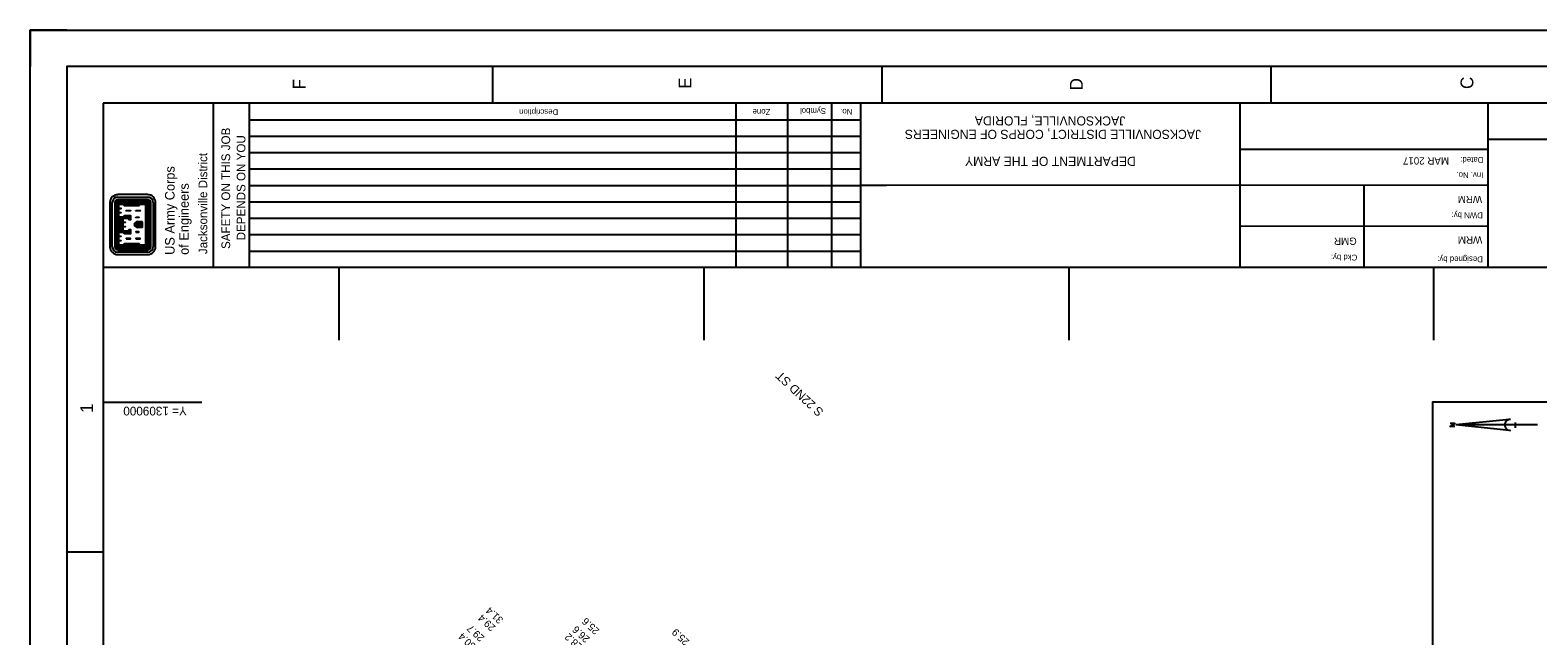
# Model space of a CAD drawing. Extents: x 515576 to 518976, y 1305110 to 1309511.
# Drawn here: x 515576 to 517642, y 1308680 to 1309510 of the extents above; entities that cross this region are included whole.
import ezdxf

# ---------------------------------------------------------------- set-up
doc = ezdxf.new("R2010")
doc.units = 0
for name, color, linetype in [('G-ANNO-NPLT', 7, 'Continuous'), ('G-ANNO-TEXT-DRWG', 7, 'Continuous'), ('G-ANNO-TEXT-LOGO', 7, 'Continuous'), ('G-ANNO-TEXT-PROJ', 7, 'Continuous'), ('G-ANNO-TEXT-TTLB', 7, 'Continuous'), ('G-ANNO-TTLB', 7, 'Continuous'), ('V-ANNO-SYMB', 7, 'Continuous'), ('V-ROAD-IDEN', 7, 'Continuous'), ('V-TOPO-COOR-STAT', 7, 'Continuous'), ('V-TOPO-SOUN', 7, 'Continuous')]:
    doc.layers.add(name, color=color, linetype=linetype)

msp = doc.modelspace()

# ---------------------------------------------------------------- linework, layer by layer
at = {"layer": 'G-ANNO-NPLT'}
msp.add_lwpolyline([(515576.5, 1305110.5), (515576.5, 1309510.4), (518976.4, 1309510.4), (518976.4, 1305110.5)], close=True, dxfattribs=at)
msp.add_lwpolyline([(515626.5, 1309510.4), (515576.5, 1309510.4), (515576.5, 1309460.4)], dxfattribs=at)
at = {"layer": 'G-ANNO-TEXT-LOGO'}
for p, q in [((515737.5, 1309285), (515696.5, 1309285)), ((515696.5, 1309281.7), (515737.5, 1309281.7)), ((515685.8, 1309274.3), (515685.8, 1309213.5)), ((515689, 1309213.5), (515689, 1309274.3)), ((515692.4, 1309274.3), (515692.4, 1309213.5)), ((515693.3, 1309274.3), (515693.3, 1309213.5)), ((515694.2, 1309274.3), (515694.2, 1309213.5)), ((515695, 1309274.3), (515695, 1309213.5)), ((515695.9, 1309274.3), (515695.9, 1309213.5)), ((515696.5, 1309278.3), (515737.5, 1309278.3)), ((515696.5, 1309277.4), (515737.5, 1309277.4)), ((515696.5, 1309276.5), (515737.5, 1309276.5)), ((515696.5, 1309275.7), (515737.5, 1309275.7)), ((515696.5, 1309274.8), (515737.5, 1309274.8)), ((515696.5, 1309273.9), (515737.2, 1309273.9)), ((515696.5, 1309273.1), (515736.3, 1309273.1)), ((515705.3, 1309272.4), (515726.1, 1309272.4)), ((515706.1, 1309271.5), (515725.2, 1309271.5)), ((515736.3, 1309273.1), (515736.3, 1309214.7)), ((515737.2, 1309273.9), (515737.2, 1309213.9)), ((515738.1, 1309274.3), (515738.1, 1309213.5)), ((515738.9, 1309274.3), (515738.9, 1309213.5)), ((515739.8, 1309274.3), (515739.8, 1309213.5)), ((515740.7, 1309274.3), (515740.7, 1309213.5)), ((515741.5, 1309274.3), (515741.5, 1309213.5)), ((515745, 1309274.3), (515745, 1309213.5)), ((515748.3, 1309213.5), (515748.3, 1309274.3)), ((515696.7, 1309234.6), (515696.7, 1309253.2)), ((515697.6, 1309234.6), (515697.6, 1309253.2)), ((515698.4, 1309234.6), (515698.4, 1309253.2)), ((515699.3, 1309234.6), (515699.3, 1309253.2)), ((515700.2, 1309234.6), (515700.2, 1309253.2)), ((515701, 1309234.6), (515701, 1309253.2)), ((515701.9, 1309234.6), (515701.9, 1309253.2)), ((515730.4, 1309247.9), (515723.7, 1309247.9)), ((515730.4, 1309247.1), (515723.7, 1309247.1)), ((515730.4, 1309246.2), (515723.7, 1309246.2)), ((515730.4, 1309245.3), (515723.7, 1309245.3)), ((515730.4, 1309244.5), (515723.7, 1309244.5)), ((515730.4, 1309243.3), (515723.7, 1309243.3)), ((515730.4, 1309242.5), (515723.7, 1309242.5)), ((515730.4, 1309241.6), (515723.7, 1309241.6)), ((515730.4, 1309240.7), (515723.7, 1309240.7)), ((515730.4, 1309239.9), (515723.7, 1309239.9)), ((515730.4, 1309239.9), (515730.4, 1309247.9)), ((515696.5, 1309214.7), (515736.3, 1309214.7)), ((515696.5, 1309213.9), (515737.2, 1309213.9)), ((515696.5, 1309213), (515737.5, 1309213)), ((515696.5, 1309212.1), (515737.5, 1309212.1)), ((515696.5, 1309211.2), (515737.5, 1309211.2)), ((515696.5, 1309210.4), (515737.5, 1309210.4)), ((515696.5, 1309209.5), (515737.5, 1309209.5)), ((515737.5, 1309206), (515696.5, 1309206)), ((515696.5, 1309202.8), (515737.5, 1309202.8)), ((515705.2, 1309215.4), (515726.2, 1309215.4)), ((515706.1, 1309216.3), (515725.2, 1309216.3))]:
    msp.add_line(p, q, dxfattribs=at)
for points in [[(515696.5, 1309215.4), (515704.4, 1309215.4), (515706.1, 1309217.1), (515725.2, 1309217.1), (515727, 1309215.4), (515735.7, 1309215.4), (515735.7, 1309272.4), (515727, 1309272.4), (515725.2, 1309270.6), (515706.1, 1309270.6), (515704.4, 1309272.4), (515696.5, 1309272.4), (515696.5, 1309264.9), (515696.5, 1309259.1), (515696.5, 1309253.7), (515704.4, 1309253.7), (515706.1, 1309255.6), (515713.1, 1309255.6), (515713.1, 1309251.4), (515712.4, 1309251.4), (515710.6, 1309253.2), (515702.8, 1309253.2), (515702.8, 1309245.7), (515702.8, 1309239.9), (515702.8, 1309234.6), (515710.6, 1309234.6), (515712.4, 1309236.4), (515713.1, 1309236.4), (515713.1, 1309232.2), (515706.1, 1309232.2), (515704.4, 1309234), (515696.5, 1309234), (515696.5, 1309226.5), (515696.5, 1309220.7), (515696.5, 1309215.4)], [(515697.4, 1309216.2), (515704, 1309216.2), (515705.8, 1309218), (515725.6, 1309218), (515727.4, 1309216.2), (515734.8, 1309216.2), (515734.8, 1309271.6), (515727.4, 1309271.6), (515725.6, 1309269.7), (515705.8, 1309269.7), (515704, 1309271.6), (515697.4, 1309271.6), (515697.4, 1309266.2), (515700.5, 1309266.2), (515700.5, 1309265.7), (515697.4, 1309265.7), (515697.4, 1309260.4), (515700.5, 1309260.4), (515700.5, 1309260), (515697.4, 1309260), (515697.4, 1309254.6), (515704, 1309254.6), (515705.8, 1309256.4), (515713.9, 1309256.4), (515713.9, 1309250.6), (515712, 1309250.6), (515710.2, 1309252.4), (515703.6, 1309252.4), (515703.6, 1309247), (515706.7, 1309247), (515706.7, 1309246.6), (515703.6, 1309246.6), (515703.6, 1309241.2), (515706.7, 1309241.2), (515706.7, 1309240.7), (515703.6, 1309240.7), (515703.6, 1309235.4), (515710.2, 1309235.4), (515712, 1309237.2), (515713.9, 1309237.2), (515713.9, 1309231.4), (515705.8, 1309231.4), (515704, 1309233.2), (515697.4, 1309233.2), (515697.4, 1309227.9), (515700.5, 1309227.9), (515700.5, 1309227.4), (515697.4, 1309227.4), (515697.4, 1309222), (515700.5, 1309222), (515700.5, 1309221.6), (515697.4, 1309221.6), (515697.4, 1309216.2)], [(515708.1, 1309263.3), (515713.9, 1309263.3), (515713.9, 1309262.8), (515708.1, 1309262.8), (515708.1, 1309263.3)], [(515721.4, 1309263.3), (515727.3, 1309263.3), (515727.3, 1309262.8), (515721.4, 1309262.8), (515721.4, 1309263.3)], [(515706, 1309254.2), (515706.5, 1309254.7), (515712.2, 1309254.7), (515712.2, 1309252.9), (515710.9, 1309254.1), (515705.9, 1309254.1)], [(515721.4, 1309254.2), (515725.5, 1309254.2), (515725.5, 1309253.7), (515721.4, 1309253.7), (515721.4, 1309254.2)], [(515706, 1309233.6), (515706.5, 1309233.1), (515712.2, 1309233.1), (515712.2, 1309235), (515710.9, 1309233.7), (515705.9, 1309233.7)], [(515708.1, 1309224.4), (515713.9, 1309224.4), (515713.9, 1309225), (515708.1, 1309225), (515708.1, 1309224.4)], [(515721.4, 1309233.6), (515725.5, 1309233.6), (515725.5, 1309234.1), (515721.4, 1309234.1), (515721.4, 1309233.6)], [(515721.4, 1309224.4), (515727.3, 1309224.4), (515727.3, 1309225), (515721.4, 1309225), (515721.4, 1309224.4)]]:
    msp.add_lwpolyline(points, dxfattribs=at)
for centre, major_axis, start_param, end_param in [((515696.5, 1309274.2), (0, 10.7), 6.283169, 7.853965), ((515696.5, 1309274.2), (0, 7.49), 6.28317, 7.853966), ((515737.6, 1309274.2), (0, 10.7), 4.712373, 6.28317), ((515737.6, 1309274.2), (0, -7.49), 1.570781, 3.141577), ((515696.5, 1309274.2), (0, 4.02), 6.283169, 7.853965), ((515696.5, 1309274.2), (0, 3.15), 6.283169, 7.853965), ((515696.5, 1309274.2), (0, 2.28), 6.283169, 7.853965), ((515696.5, 1309274.2), (0, 1.41), 6.283169, 7.853965), ((515696.5, 1309274.2), (0, 0.546), 6.283169, 7.853965), ((515737.6, 1309274.2), (0, 4.02), 4.712373, 6.28317), ((515737.6, 1309274.2), (0, 3.15), 4.712373, 6.28317), ((515737.6, 1309274.2), (0, 2.28), 4.712373, 6.28317), ((515737.6, 1309274.2), (0, 1.41), 4.712373, 6.28317), ((515737.6, 1309274.2), (0, 0.546), 4.712373, 6.28317), ((515724.2, 1309242.4), (0, 5.55), 0.068795, 1.29842), ((515724.2, 1309245.4), (0, -5.55), 4.985832, 6.214359), ((515724.2, 1309242.4), (0, 4.69), 0.068795, 1.335689), ((515724.2, 1309245.4), (0, -4.69), 4.947465, 6.21436), ((515724.2, 1309242.4), (0, 3.82), 0.068795, 1.335689), ((515724.2, 1309245.4), (0, -3.82), 4.947465, 6.21436), ((515724.2, 1309242.4), (0, 2.95), 0.068794, 1.335689), ((515724.2, 1309245.4), (0, -2.95), 4.947465, 6.21436), ((515724.2, 1309245.4), (0, -2.08), 4.947465, 6.214359), ((515724.2, 1309242.4), (0, 2.08), 0.068794, 1.335689), ((515696.5, 1309213.5), (0, 10.7), 1.57078, 3.141576), ((515696.5, 1309213.5), (0, 7.49), 1.57078, 3.141576), ((515696.5, 1309213.5), (0, 4.02), 1.57078, 3.141576), ((515696.5, 1309213.5), (0, 3.15), 1.57078, 3.141576), ((515696.5, 1309213.5), (0, 2.28), 1.57078, 3.141576), ((515696.5, 1309213.5), (0, 1.41), 1.57078, 3.141576), ((515696.5, 1309213.5), (0, 0.546), 1.57078, 3.141576), ((515737.6, 1309213.5), (0, -4.02), 6.28317, 7.853966), ((515737.6, 1309213.5), (0, -3.15), 6.28317, 7.853966), ((515737.6, 1309213.5), (0, -2.28), 6.28317, 7.853966), ((515737.6, 1309213.5), (0, -1.41), 6.28317, 7.853966), ((515737.6, 1309213.5), (0, -0.546), 6.28317, 7.853966), ((515737.6, 1309213.5), (0, -10.7), 6.28317, 7.853966), ((515737.6, 1309213.5), (0, -7.49), 6.28317, 7.853966)]:
    msp.add_ellipse(centre, major_axis=major_axis, ratio=0.99964, start_param=start_param, end_param=end_param, dxfattribs=at)
at = {"layer": 'G-ANNO-TTLB'}
for p, q in [((516210, 1309460.4), (516210, 1309410.4)), ((516743.3, 1309460.4), (516743.3, 1309410.4)), ((517276.6, 1309460.4), (517276.6, 1309410.4)), ((515827.7, 1309185.4), (515827.7, 1309410.4)), ((515876.8, 1309184.8), (515876.8, 1309409.8)), ((516543.7, 1309185.4), (516543.7, 1309410.4)), ((516614.9, 1309185.4), (516614.9, 1309410.4)), ((516674.9, 1309185.4), (516674.9, 1309410.4)), ((516714.7, 1309185.4), (516714.7, 1309410.4)), ((517234.6, 1309184.6), (517234.6, 1309410.4)), ((517574.3, 1309184.2), (517574.3, 1309410.4)), ((515876.8, 1309387.7), (516714.7, 1309387.7)), ((515876.8, 1309365.2), (516714.7, 1309365.2)), ((515876.8, 1309342.7), (516714.7, 1309342.7)), ((517234.6, 1309347.5), (517574.3, 1309347.5)), ((517574.3, 1309361.1), (517925.7, 1309361.1)), ((515876.8, 1309320.2), (516714.7, 1309320.2)), ((515876.8, 1309297.7), (516714.7, 1309297.7)), ((517574.3, 1309297.3), (516714.7, 1309297.9)), ((516714.7, 1309297.9), (516750.1, 1309297.9)), ((517404.5, 1309184.6), (517404.5, 1309297.4)), ((515876.8, 1309275.2), (516714.7, 1309275.2)), ((515876.8, 1309252.7), (516714.7, 1309252.7)), ((517574.3, 1309241.3), (517234.6, 1309241.6)), ((515876.8, 1309230.2), (516714.7, 1309230.2)), ((515876.8, 1309207.7), (516714.7, 1309207.7)), ((515676.5, 1309185.4), (518876.4, 1309185.4)), ((515626.5, 1308795.4), (515676.5, 1308795.4))]:
    msp.add_line(p, q, dxfattribs=at)
for points in [[(518926.4, 1305160.5), (518926.4, 1309460.4), (515626.5, 1309460.4), (515626.5, 1305160.5)], [(515676.5, 1309410.4), (515676.5, 1305285.5), (518876.4, 1305285.5), (518876.4, 1309410.4)]]:
    msp.add_lwpolyline(points, close=True, dxfattribs=at)
at = {"layer": 'V-ANNO-SYMB'}
for p, q in [((517603.7, 1308976.7), (517530, 1308969.3)), ((517611.5, 1308972.8), (517611.5, 1308965.3)), ((517641.7, 1308969.3), (517530, 1308969.3)), ((517603.7, 1308961.8), (517530, 1308969.3))]:
    msp.add_line(p, q, dxfattribs=at)
msp.add_lwpolyline([(517498.3, 1308383.7), (517498.3, 1309001), (518190.8, 1309001), (518190.8, 1308383.7)], close=True, dxfattribs=at)
msp.add_lwpolyline([(517528.8, 1308967.2), (517522.3, 1308967.2), (517528.8, 1308971.2), (517522.3, 1308971.2)], dxfattribs=at)
msp.add_arc((517604.5, 1308969.3), 7.45, 85.2984, 272.0673, dxfattribs=at)
at = {"layer": 'V-TOPO-COOR-STAT'}
for p, q in [((516000, 1309085.4), (516000, 1309185.4)), ((516500, 1309085.4), (516500, 1309185.4)), ((517000, 1309085.4), (517000, 1309185.4)), ((517500, 1309085.4), (517500, 1309185.4)), ((515811.5, 1309000), (515676.5, 1309000))]:
    msp.add_line(p, q, dxfattribs=at)

# ---------------------------------------------------------------- texts
at = {"layer": 'G-ANNO-TEXT-DRWG'}
for s, p in [('WRM', (517566, 1309283.3)), ('GMR', (517394.2, 1309226.1)), ('WRM', (517566.2, 1309227.7))]:
    msp.add_text(s, height=10, rotation=180, dxfattribs=at).set_placement(p)
at = {"layer": 'G-ANNO-TEXT-PROJ'}
msp.add_text('MAR 2017', height=10, rotation=180, dxfattribs=at).set_placement((517520.7, 1309336.2))
at = {"layer": 'G-ANNO-TEXT-TTLB'}
for s, height, rotation, p in [('Symbol', 8, 180, (516667, 1309403.5)), ('Description', 8, 180, (516300, 1309402)), ('Zone', 8, 180, (516590.7, 1309402.3)), ('No.', 8, 180, (516703.1, 1309402.5)), ('JACKSONVILLE, FLORIDA', 12.5, 180, (517077.1, 1309392.3)), ('SAFETY ON THIS JOB', 11.9, 90, (515850.5, 1309210.5)), ('DEPENDS ON YOU', 11.9, 90, (515871.4, 1309222.3)), ('JACKSONVILLE DISTRICT, CORPS OF ENGINEERS', 12.5, 180, (517180.9, 1309373.8)), ('US Army Corps', 13.086, 90, (515774.4, 1309202.4)), ('Jacksonville District', 11.9, 90, (515819.1, 1309203.4)), ('DEPARTMENT OF THE ARMY', 12.5, 180, (517091.5, 1309336.8)), ('Dated:', 8, 180, (517567.6, 1309336.5)), ('Inv. No.', 8, 180, (517567.7, 1309315.7)), ('of Engineers', 13.086, 90, (515793.8, 1309202.4)), ('DWN by:', 8, 180, (517567, 1309260.5)), ('Ckd by:', 8, 180, (517395, 1309202.7)), ('Designed by:', 8, 180, (517567, 1309200.2))]:
    msp.add_text(s, height=height, rotation=rotation, dxfattribs=at).set_placement(p)
at = {"layer": 'G-ANNO-TTLB'}
for s, p in [('F', (515953.8, 1309429.2)), ('E', (516482.6, 1309430)), ('D', (517018.7, 1309427.8)), ('C', (517554, 1309429.7)), ('1', (515662.6, 1308985.8))]:
    msp.add_text(s, height=17.5, rotation=90, dxfattribs=at).set_placement(p)
at = {"layer": 'V-ROAD-IDEN'}
msp.add_text('S 22ND ST', height=12, rotation=137.0497, dxfattribs=at).set_placement((516664.6, 1308988.5))
at = {"layer": 'V-TOPO-COOR-STAT'}
msp.add_text('Y= 1309000', height=12, rotation=180, dxfattribs=at).set_placement((515791.1, 1308994.3))
at = {"layer": 'V-TOPO-SOUN'}
for s, p in [('29.4 ', (516214.9, 1308692.8)), ('31.4 ', (516225.6, 1308703)), ('25.6 ', (516357.3, 1308688.2)), ('30.4 ', (516187.9, 1308667.4)), ('29.7 ', (516199.7, 1308678.5)), ('28.2 ', (516333.8, 1308666.8)), ('26.6 ', (516344.1, 1308676.9)), ('25.9 ', (516480.5, 1308673.3))]:
    msp.add_text(s, height=10, rotation=136.9626, dxfattribs=at).set_placement(p)

doc.saveas('drawing.dxf')
